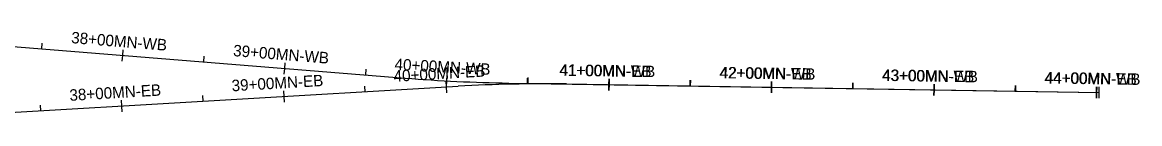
# Model space of a CAD drawing. Extents: x 596007 to 607538, y 326212 to 405053.
# Drawn here: x 603002 to 603689, y 366104 to 366154 of the extents above; entities that cross this region are included whole.
import ezdxf

# ---------------------------------------------------------------- set-up
doc = ezdxf.new("R2010")
doc.units = 0
doc.layers.add('P_ALI_200', color=7, linetype='Continuous')
doc.layers.add('P_ALI_200_Sta', color=7, linetype='Continuous')

msp = doc.modelspace()

# ---------------------------------------------------------------- linework, layer by layer
at = {"layer": 'P_ALI_200'}
for points in [[(602960.44, 366147.81), (603237.59, 366125.7)], [(602976.81, 366103.55), (603270.16, 366120.67)], [(603301.27, 366122.66), (603664.46, 366116.9)], [(603336.89, 366122.09), (603664.46, 366116.9)]]:
    msp.add_lwpolyline(points, dxfattribs=at)
for centre, radius, start, end in [((603317.12, 367122.53), 1000, 265.43841, 269.09187), ((603322.62, 365222.2), 900, 89.09187, 93.34187)]:
    msp.add_arc(centre, radius, start, end, dxfattribs=at)
at = {"layer": 'P_ALI_200_Sta'}
for points in [[(603013.96, 366143.54), (603014.24, 366147.03)], [(603063.53, 366136.07), (603063.8, 366139.56)], [(603063.8, 366139.56), (603064.08, 366143.05)], [(603063.8, 366139.56), (603063.8, 366139.56)], [(603113.65, 366135.59), (603113.92, 366139.08)], [(603163.49, 366131.61), (603163.77, 366135.1)], [(603163.21, 366128.12), (603163.49, 366131.61)], [(603163.49, 366131.61), (603163.49, 366131.61)], [(603213.33, 366127.63), (603213.61, 366131.12)], [(603263.19, 366123.99), (603263.38, 366127.48)], [(603312.9, 366122.15), (603312.87, 366125.65)], [(603313.17, 366122.47), (603313.22, 366125.97)], [(603362.9, 366121.68), (603362.96, 366125.18)], [(603363.16, 366121.68), (603363.22, 366125.17)], [(603213.03, 366117.34), (603212.83, 366120.83)], [(603262.95, 366120.25), (603262.74, 366123.75)], [(603262.95, 366120.25), (603262.95, 366120.25)], [(603263.15, 366116.76), (603262.95, 366120.25)], [(603263.01, 366120.49), (603263.19, 366123.99)], [(603263.19, 366123.99), (603263.19, 366123.99)], [(603362.84, 366118.18), (603362.9, 366121.68)], [(603362.9, 366121.68), (603362.9, 366121.68)], [(603363.11, 366118.18), (603363.16, 366121.68)], [(603363.16, 366121.68), (603363.16, 366121.68)], [(603412.89, 366120.89), (603412.95, 366124.39)], [(603413.15, 366120.88), (603413.21, 366124.38)], [(603462.83, 366116.6), (603462.89, 366120.09)], [(603462.89, 366120.09), (603462.94, 366123.59)], [(603462.89, 366120.09), (603462.89, 366120.09)], [(603463.09, 366116.59), (603463.15, 366120.09)], [(603463.15, 366120.09), (603463.2, 366123.59)], [(603463.15, 366120.09), (603463.15, 366120.09)], [(603512.88, 366119.3), (603512.94, 366122.8)], [(603513.14, 366119.3), (603513.2, 366122.8)], [(603562.82, 366115.01), (603562.88, 366118.51)], [(603562.88, 366118.51), (603562.93, 366122.01)], [(603562.88, 366118.51), (603562.88, 366118.51)], [(603563.08, 366115.01), (603563.14, 366118.51)], [(603563.14, 366118.51), (603563.19, 366122.01)], [(603563.14, 366118.51), (603563.14, 366118.51)], [(603612.87, 366117.72), (603612.92, 366121.22)], [(603613.13, 366117.71), (603613.19, 366121.21)], [(603662.86, 366116.92), (603662.92, 366120.42)], [(603663.12, 366116.92), (603663.18, 366120.42)], [(603664.46, 366116.9), (603664.52, 366120.4)], [(603664.46, 366116.9), (603664.52, 366120.4)], [(603063.29, 366108.59), (603063.08, 366112.09)], [(603113.2, 366111.51), (603113, 366115)], [(603163.12, 366114.42), (603162.91, 366117.92)], [(603163.12, 366114.42), (603163.12, 366114.42)], [(603163.32, 366110.93), (603163.12, 366114.42)], [(603662.81, 366113.43), (603662.86, 366116.92)], [(603662.86, 366116.92), (603662.86, 366116.92)], [(603663.07, 366113.42), (603663.12, 366116.92)], [(603663.12, 366116.92), (603663.12, 366116.92)], [(603664.41, 366113.4), (603664.46, 366116.9)], [(603664.41, 366113.4), (603664.46, 366116.9)], [(603664.46, 366116.9), (603664.46, 366116.9)], [(603664.46, 366116.9), (603664.46, 366116.9)], [(603013.37, 366105.68), (603013.17, 366109.17)], [(603063.29, 366108.59), (603063.29, 366108.59)], [(603063.49, 366105.1), (603063.29, 366108.59)]]:
    msp.add_lwpolyline(points, dxfattribs=at)

# ---------------------------------------------------------------- texts
for s, height, rotation, p in [('38+00MN-WB', 7, 355.43841, (603031.91, 366147.12)), ('39+00MN-WB', 7, 355.43841, (603131.54, 366139.18)), ('40+00MN-EB', 7, 3.34187, (603230.64, 366123.38)), ('40+00MN-WB', 7, 356.9088, (603230.88, 366130.74)), ('41+00MN-WB', 7, 359.09187, (603332.31, 366127.17)), ('41+00MN-EB', 7, 359.09187, (603332.62, 366127.16)), ('42+00MN-WB', 7, 359.09187, (603430.83, 366125.6)), ('42+00MN-EB', 7, 359.09187, (603431.14, 366125.6)), ('39+00MN-EB', 7, 3.34187, (603131, 366117.56)), ('43+00MN-WB', 7, 359.09187, (603530.82, 366124.02)), ('43+00MN-EB', 7, 359.09187, (603531.13, 366124.01)), ('44+00MN-WB', 7, 359.09187, (603630.81, 366122.43)), ('44+00MN-EB', 7, 359.09187, (603631.11, 366122.43)), ('38+00MN-EB', 7, 3.34187, (603031.22, 366111.73)), ('44+01MN-WB', 0.0000000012, 359.09187, (603664.54, 366121.9)), ('44+02MN-EB', 0.0000000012, 359.09187, (603664.54, 366121.9))]:
    msp.add_text(s, height=height, rotation=rotation, dxfattribs=at).set_placement(p)

doc.saveas('drawing.dxf')
